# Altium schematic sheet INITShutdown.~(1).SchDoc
size A4
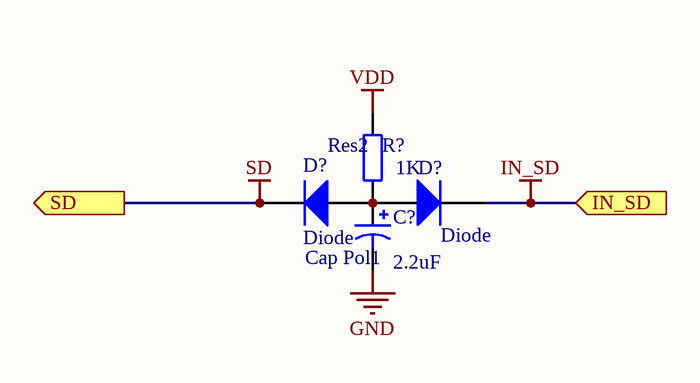
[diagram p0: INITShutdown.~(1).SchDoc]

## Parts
(Parts that share a designator on the sheet are numbered #1, #2 ... from top to bottom, then left to right.)
C?  Cap Pol1  value 2.2uF  [RB7.6-15]
D?#1  Diode  [SMC]
D?#2  Diode  [SMC]
R?  Res2  value 1K  [AXIAL-0.4]

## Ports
IN_SD (in), SD (out)

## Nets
GND: C?.2
IN_SD: D?#1.2(K) ; port IN_SD
SD: D?#2.2(K) ; port SD
VDD: R?.2
NetC?_1: C?.1 D?#1.1(A) D?#2.1(A) R?.1

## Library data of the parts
C? = Cap Pol1: Polarized Capacitor (Radial)
D?#1 D?#2 = Diode: Default Diode
R? = Res2: Resistor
